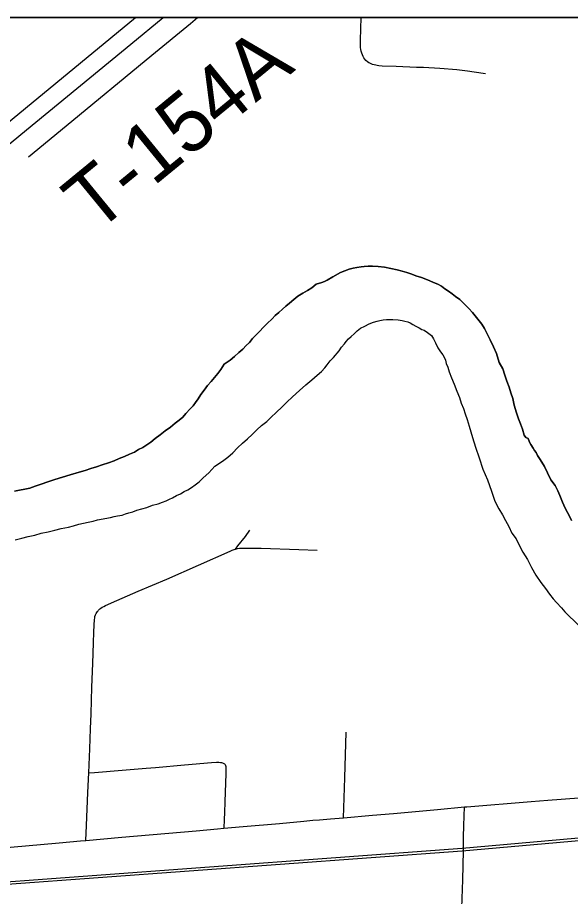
# Model space of a CAD drawing. Extents: x -483 to 680, y 0 to 440.
# Drawn here: x 226.42 to 252.91, y 353.88 to 395.95 of the extents above; entities that cross this region are included whole.
import ezdxf

# ---------------------------------------------------------------- set-up
doc = ezdxf.new("R2010")
doc.units = 0
for name, color, linetype in [('GM_X_City_Street', 7, 'Continuous'), ('GM_X_County_Road', 7, 'Continuous'), ('GM_X_Major_River', 7, 'Continuous'), ('GM_X_Rail_Line', 7, 'Continuous'), ('GM_X_Township_Road', 7, 'Continuous'), ('GM_X_Township_Road_Text', 7, 'Continuous'), ('GM_X_US_Route', 7, 'Continuous'), ('SH_Cut_Line', 7, 'Continuous'), ('SH_Text', 7, 'Continuous')]:
    doc.layers.add(name, color=color, linetype=linetype)

msp = doc.modelspace()

# ---------------------------------------------------------------- linework, layer by layer
at = {"layer": 'GM_X_City_Street'}
for points in [[(236.867, 370.51), (236.981, 370.655), (237.338, 371.112), (237.555, 371.41)], [(229.691, 356.565), (229.72, 357.268), (229.787, 358.859), (229.833, 359.797), (229.878, 360.945), (229.919, 361.898), (229.942, 362.622), (229.978, 363.895), (230.023, 365.032), (230.063, 366.023), (230.079, 366.525), (230.095, 366.862), (230.109, 367.137), (230.118, 367.201), (230.129, 367.273), (230.157, 367.359), (230.185, 367.417), (230.214, 367.468), (230.249, 367.518), (230.28, 367.555), (230.3, 367.579), (230.329, 367.608), (230.37, 367.643), (230.417, 367.68), (230.481, 367.722), (230.553, 367.763), (230.639, 367.805), (231.179, 368.042), (232.204, 368.487), (233.575, 369.073), (236.614, 370.415), (236.699, 370.448), (236.792, 370.485), (236.867, 370.51), (236.965, 370.533), (237.058, 370.546), (237.15, 370.55), (237.492, 370.553), (238.086, 370.545), (239.89, 370.494), (240.774, 370.462)], [(242.045, 357.645), (242.102, 359.552), (242.168, 361.741)], [(231.427, 359.917), (232.591, 360.017), (233.032, 360.054), (234.419, 360.182), (235.713, 360.287), (235.948, 360.301), (236.058, 360.304), (236.141, 360.297), (236.2, 360.287), (236.24, 360.275), (236.273, 360.263), (236.305, 360.244), (236.334, 360.223), (236.363, 360.197), (236.39, 360.152), (236.404, 360.094), (236.404, 360.049), (236.404, 359.987), (236.398, 359.771), (236.35, 358.406), (236.33, 357.9), (236.317, 357.558), (236.301, 357.146)], [(229.833, 359.797), (230.111, 359.818), (231.427, 359.917)], [(247.69, 352.678), (247.71, 353.329), (247.75, 354.672), (247.782, 356.062), (247.793, 356.718), (247.802, 357.277), (247.829, 358.163)]]:
    msp.add_lwpolyline(points, dxfattribs=at)
at = {"layer": 'GM_X_County_Road'}
for points in [[(251.82, 358.489), (253.312, 358.607), (254.357, 358.688), (257.026, 358.902)], [(247.829, 358.163), (247.944, 358.173), (251.024, 358.426), (251.82, 358.489)], [(242.045, 357.645), (243.42, 357.768), (244.44, 357.853), (246.548, 358.041), (247.829, 358.163)], [(236.301, 357.146), (237.231, 357.222), (238.964, 357.379), (240.137, 357.477), (240.571, 357.523), (240.886, 357.548), (241.408, 357.589), (242.045, 357.645)], [(229.691, 356.565), (231.412, 356.711), (234.972, 357.023), (235.994, 357.121), (236.301, 357.146)], [(205.564, 353.935), (206.643, 354.063), (208.428, 354.314), (210.423, 354.623), (211.709, 354.85), (212.757, 354.996), (214.54, 355.211), (216.405, 355.37), (218.975, 355.594), (220.273, 355.721), (221.078, 355.802), (222.285, 355.9), (224.792, 356.123), (226.091, 356.246), (228.412, 356.45), (229.432, 356.543), (229.691, 356.565)]]:
    msp.add_lwpolyline(points, dxfattribs=at)
at = {"layer": 'GM_X_Major_River'}
for points in [[(252.966, 371.875), (252.876, 372.049), (252.767, 372.26), (252.658, 372.472), (252.533, 372.76), (252.407, 373.067), (252.299, 373.297), (252.173, 373.548), (251.97, 373.819), (251.808, 374.165), (251.663, 374.453), (251.536, 374.665), (251.426, 374.839), (251.335, 374.993), (251.262, 375.128), (251.189, 375.225), (251.116, 375.341), (251.006, 375.514), (250.952, 375.629), (250.88, 375.802), (250.767, 375.843), (250.694, 375.959), (250.607, 376.246), (250.518, 376.495), (250.429, 376.744), (250.322, 377.032), (250.218, 377.395), (250.15, 377.72), (250.061, 377.988), (249.973, 378.256), (249.866, 378.544), (249.76, 378.831), (249.672, 379.137), (249.49, 379.446), (249.368, 379.867), (249.224, 380.193), (249.061, 380.52), (248.917, 380.809), (248.79, 381.059), (248.662, 381.271), (248.22, 381.833), (248.035, 382.027), (247.85, 382.222), (247.609, 382.456), (247.404, 382.594), (247.236, 382.731), (247.068, 382.85), (246.9, 382.968), (246.732, 383.086), (246.564, 383.185), (246.357, 383.266), (246.169, 383.347), (245.981, 383.428), (245.774, 383.509), (245.51, 383.592), (245.304, 383.673), (245.078, 383.754), (244.851, 383.817), (244.606, 383.88), (244.304, 383.945), (244.002, 384.01), (243.698, 384.036), (243.433, 384.043), (243.224, 384.048), (243.033, 384.034), (242.881, 384.019), (242.671, 383.986), (242.5, 383.953), (242.308, 383.901), (241.887, 383.74), (241.521, 383.541), (241.251, 383.377), (241.135, 383.323), (241.001, 383.269), (240.733, 383.181), (240.52, 383.015), (240.308, 382.888), (240.096, 382.76), (239.845, 382.615)], [(239.845, 382.615), (240.096, 382.76), (240.308, 382.888), (240.52, 383.015), (240.733, 383.181), (241.001, 383.269), (241.135, 383.323), (241.251, 383.377), (241.521, 383.541), (241.887, 383.74), (242.308, 383.901), (242.5, 383.953), (242.671, 383.986), (242.881, 384.019), (243.033, 384.034), (243.224, 384.048), (243.433, 384.043), (243.698, 384.036), (244.002, 384.01), (244.304, 383.945), (244.606, 383.88), (244.851, 383.817), (245.078, 383.754), (245.304, 383.673), (245.51, 383.592), (245.774, 383.509), (245.981, 383.428), (246.169, 383.347), (246.357, 383.266), (246.564, 383.185), (246.732, 383.086), (246.9, 382.968), (247.068, 382.85), (247.236, 382.731), (247.404, 382.594), (247.609, 382.456), (247.85, 382.222), (248.035, 382.027), (248.22, 381.833), (248.662, 381.271), (248.79, 381.059), (248.917, 380.809), (249.061, 380.52), (249.224, 380.193), (249.368, 379.867), (249.49, 379.446), (249.672, 379.137), (249.76, 378.831), (249.866, 378.544), (249.973, 378.256), (250.061, 377.988), (250.15, 377.72), (250.218, 377.395), (250.322, 377.032), (250.429, 376.744), (250.518, 376.495), (250.607, 376.246), (250.694, 375.959), (250.767, 375.843), (250.88, 375.802), (250.952, 375.629), (251.006, 375.514), (251.116, 375.341), (251.189, 375.225), (251.262, 375.128), (251.335, 374.993), (251.426, 374.839), (251.536, 374.665), (251.663, 374.453), (251.808, 374.165), (251.97, 373.819), (252.173, 373.548), (252.299, 373.297), (252.407, 373.067), (252.533, 372.76), (252.658, 372.472), (252.767, 372.26), (252.876, 372.049), (252.966, 371.875)], [(239.845, 382.615), (239.651, 382.449), (239.457, 382.283), (239.282, 382.135), (239.108, 381.988), (238.933, 381.84), (238.758, 381.693), (238.621, 381.525), (238.388, 381.303), (237.842, 380.747), (237.686, 380.58), (237.529, 380.394), (237.374, 380.246), (237.217, 380.079), (237.024, 379.913), (236.81, 379.729), (236.615, 379.544), (236.326, 379.361), (236.167, 379.099), (236.011, 378.913), (235.854, 378.728), (235.697, 378.523), (235.522, 378.337), (235.364, 378.113), (235.207, 377.908), (235.069, 377.703), (234.95, 377.516), (234.833, 377.367), (234.696, 377.219), (234.481, 376.996), (234.344, 376.829), (234.17, 376.681), (233.976, 376.534), (233.743, 376.35), (233.492, 376.167), (233.259, 375.983), (233.008, 375.799), (232.814, 375.633), (232.621, 375.505), (232.428, 375.377), (232.216, 375.268), (232.023, 375.14), (231.793, 375.051), (231.543, 374.944), (231.293, 374.836), (231.044, 374.728), (230.776, 374.64), (230.469, 374.534), (230.201, 374.446), (229.933, 374.358), (229.665, 374.269), (229.378, 374.182), (228.938, 374.06), (228.574, 373.955), (228.21, 373.832), (227.866, 373.726), (227.559, 373.62), (227.272, 373.513), (227.004, 373.425), (226.278, 373.273)], [(226.278, 373.273), (227.004, 373.425), (227.272, 373.513), (227.559, 373.62), (227.866, 373.726), (228.21, 373.832), (228.574, 373.955), (228.938, 374.06), (229.378, 374.182), (229.665, 374.269), (229.933, 374.358), (230.201, 374.446), (230.469, 374.534), (230.776, 374.64), (231.044, 374.728), (231.293, 374.836), (231.543, 374.944), (231.793, 375.051), (232.023, 375.14), (232.216, 375.268), (232.428, 375.377), (232.621, 375.505), (232.814, 375.633), (233.008, 375.799), (233.259, 375.983), (233.492, 376.167), (233.743, 376.35), (233.976, 376.534), (234.17, 376.681), (234.344, 376.829), (234.481, 376.996), (234.696, 377.219), (234.833, 377.367), (234.95, 377.516), (235.069, 377.703), (235.207, 377.908), (235.364, 378.113), (235.522, 378.337), (235.697, 378.523), (235.854, 378.728), (236.011, 378.913), (236.167, 379.099), (236.326, 379.361), (236.615, 379.544), (236.81, 379.729), (237.024, 379.913), (237.217, 380.079), (237.374, 380.246), (237.529, 380.394), (237.686, 380.58), (237.842, 380.747), (238.388, 381.303), (238.621, 381.525), (238.758, 381.693), (238.933, 381.84), (239.108, 381.988), (239.282, 382.135), (239.457, 382.283), (239.651, 382.449), (239.845, 382.615)], [(226.315, 370.955), (226.621, 371.023), (226.927, 371.11), (227.251, 371.178), (227.557, 371.265), (227.882, 371.333), (228.207, 371.42), (228.513, 371.488), (228.856, 371.555), (229.105, 371.625), (229.353, 371.695), (229.583, 371.746), (229.812, 371.797), (230.041, 371.848), (230.251, 371.9), (230.881, 372.017), (231.053, 372.069), (231.206, 372.103), (231.435, 372.136), (231.588, 372.189), (231.76, 372.241), (231.951, 372.294), (232.143, 372.365), (232.373, 372.435), (232.622, 372.504), (232.89, 372.611), (233.158, 372.681), (233.368, 372.751), (233.541, 372.823), (233.695, 372.895), (233.849, 372.967), (234.041, 373.076), (234.233, 373.147), (234.407, 373.257), (234.58, 373.347), (234.754, 373.457), (234.928, 373.585), (235.121, 373.733), (235.316, 373.917), (235.588, 374.158), (235.881, 374.473), (236.247, 374.711), (236.499, 374.913), (236.732, 375.116), (236.966, 375.357), (237.2, 375.579), (237.433, 375.782), (237.666, 375.985), (237.88, 376.208), (238.114, 376.429), (238.365, 376.613), (238.56, 376.798), (238.832, 377.057), (239.085, 377.297), (239.319, 377.538), (239.592, 377.797), (239.922, 378.093), (240.233, 378.37), (240.524, 378.609), (240.776, 378.831), (240.99, 379.015), (241.146, 379.182), (241.263, 379.331), (241.401, 379.518), (241.557, 379.685), (241.831, 380.001), (241.949, 380.169), (242.086, 380.336), (242.165, 380.448), (242.282, 380.578), (242.399, 380.689), (242.554, 380.818), (242.69, 380.947), (242.845, 381.076), (243.057, 381.185), (243.269, 381.294), (243.479, 381.364), (243.652, 381.417), (243.785, 381.451), (243.938, 381.485), (244.091, 381.501), (244.242, 381.497), (244.394, 381.493), (244.66, 381.486), (244.849, 381.443), (244.981, 381.421), (245.113, 381.38), (245.226, 381.339), (245.357, 381.26), (245.507, 381.18)], [(226.315, 370.955), (226.621, 371.023), (226.927, 371.11), (227.251, 371.178), (227.557, 371.265), (227.882, 371.333), (228.207, 371.42), (228.513, 371.488), (228.856, 371.555), (229.105, 371.625), (229.353, 371.695), (229.583, 371.746), (229.812, 371.797), (230.041, 371.848), (230.251, 371.9), (230.881, 372.017), (231.053, 372.069), (231.206, 372.103), (231.435, 372.136), (231.588, 372.189), (231.76, 372.241), (231.951, 372.294), (232.143, 372.365), (232.373, 372.435), (232.622, 372.504), (232.89, 372.611), (233.158, 372.681), (233.368, 372.751), (233.541, 372.823), (233.695, 372.895), (233.849, 372.967), (234.041, 373.076), (234.233, 373.147), (234.407, 373.257), (234.58, 373.347), (234.754, 373.457), (234.928, 373.585), (235.121, 373.733), (235.316, 373.917), (235.588, 374.158), (235.881, 374.473), (236.247, 374.711), (236.499, 374.913), (236.732, 375.116), (236.966, 375.357), (237.2, 375.579), (237.433, 375.782), (237.666, 375.985), (237.88, 376.208), (238.114, 376.429), (238.365, 376.613), (238.56, 376.798), (238.832, 377.057), (239.085, 377.297), (239.319, 377.538), (239.592, 377.797), (239.922, 378.093), (240.233, 378.37), (240.524, 378.609), (240.776, 378.831), (240.99, 379.015), (241.146, 379.182), (241.263, 379.331), (241.401, 379.518), (241.557, 379.685), (241.831, 380.001), (241.949, 380.169), (242.086, 380.336), (242.165, 380.448), (242.282, 380.578), (242.399, 380.689), (242.554, 380.818), (242.69, 380.947), (242.845, 381.076), (243.057, 381.185), (243.269, 381.294), (243.479, 381.364), (243.652, 381.417), (243.785, 381.451), (243.938, 381.485), (244.091, 381.501), (244.242, 381.497), (244.394, 381.493), (244.66, 381.486), (244.849, 381.443), (244.981, 381.421), (245.113, 381.38), (245.226, 381.339), (245.357, 381.26), (245.507, 381.18)], [(245.507, 381.18), (245.657, 381.1), (245.788, 381.021), (245.901, 380.98), (246.069, 380.881), (246.255, 380.724), (246.347, 380.57), (246.437, 380.378), (246.564, 380.147), (246.692, 379.953), (246.802, 379.799), (246.875, 379.664), (246.929, 379.549), (246.963, 379.396), (247.034, 379.223), (247.105, 378.993), (247.211, 378.706), (247.337, 378.399), (247.462, 378.073), (247.587, 377.766), (247.675, 377.498), (247.782, 377.229), (247.871, 376.98), (247.959, 376.712), (248.065, 376.386), (248.223, 375.851), (248.363, 375.391), (248.54, 374.874), (248.717, 374.338), (248.932, 373.82), (249.127, 373.283), (249.286, 372.804), (249.486, 372.438), (249.649, 372.149), (249.795, 371.88), (249.958, 371.591), (250.102, 371.264), (250.304, 370.993), (250.467, 370.666), (250.63, 370.358), (250.849, 370.011), (251.049, 369.626), (251.249, 369.26), (251.487, 368.912), (251.707, 368.622), (251.909, 368.351), (252.075, 368.119), (252.241, 367.944), (252.482, 367.69), (252.648, 367.496), (253.316, 366.853)], [(245.507, 381.18), (245.657, 381.1), (245.788, 381.021), (245.901, 380.98), (246.069, 380.881), (246.255, 380.724), (246.347, 380.57), (246.437, 380.378), (246.564, 380.147), (246.692, 379.953), (246.802, 379.799), (246.875, 379.664), (246.929, 379.549), (246.963, 379.396), (247.034, 379.223), (247.105, 378.993), (247.211, 378.706), (247.337, 378.399), (247.462, 378.073), (247.587, 377.766), (247.675, 377.498), (247.782, 377.229), (247.871, 376.98), (247.959, 376.712), (248.065, 376.386), (248.223, 375.851), (248.363, 375.391), (248.54, 374.874), (248.717, 374.338), (248.932, 373.82), (249.127, 373.283), (249.286, 372.804), (249.486, 372.438), (249.649, 372.149), (249.795, 371.88), (249.958, 371.591), (250.102, 371.264), (250.304, 370.993), (250.467, 370.666), (250.63, 370.358), (250.849, 370.011), (251.049, 369.626), (251.249, 369.26), (251.487, 368.912), (251.707, 368.622), (251.909, 368.351), (252.075, 368.119), (252.241, 367.944), (252.482, 367.69), (252.648, 367.496), (253.316, 366.853)]]:
    msp.add_lwpolyline(points, dxfattribs=at)
at = {"layer": 'GM_X_Rail_Line'}
for points in [[(192.002, 351.898), (217.44, 353.96), (247.719, 356.19), (265.52, 357.763), (271.346, 358.204), (275.686, 358.582), (279.482, 359.105), (282.993, 359.77), (284.746, 360.25), (290.709, 361.561), (295.027, 362.596), (299.03, 363.462), (304.742, 364.758), (307.834, 365.462), (310.741, 366.066), (314.003, 366.596), (317.177, 366.86), (319.571, 366.986), (330.057, 366.697), (343.63, 366.245), (363.661, 365.604), (385.277, 364.912), (385.608, 364.901)], [(192.012, 351.774), (217.193, 353.826), (247.729, 356.066), (265.613, 357.65), (271.48, 358.071), (275.702, 358.458), (279.502, 358.983), (283.021, 359.649), (284.775, 360.129), (290.737, 361.44), (295.055, 362.475), (299.057, 363.34), (304.769, 364.637), (307.861, 365.341), (310.764, 365.944), (314.018, 366.472), (317.185, 366.736), (319.573, 366.862), (330.054, 366.573), (343.626, 366.12), (363.658, 365.479), (385.273, 364.788), (385.608, 364.776)]]:
    msp.add_lwpolyline(points, dxfattribs=at)
at = {"layer": 'GM_X_Township_Road'}
for points in [[(226.948, 389.291), (228.745, 390.774), (232.848, 394.152), (234.701, 395.667), (235.044, 395.95)], [(245.877, 393.553), (245.528, 393.566), (244.568, 393.605), (243.886, 393.629), (243.733, 393.641), (243.656, 393.649), (243.579, 393.664), (243.5, 393.683), (243.431, 393.703), (243.36, 393.729), (243.292, 393.761), (243.247, 393.788), (243.182, 393.839), (243.108, 393.902), (243.057, 393.959), (243.012, 394.024), (242.972, 394.092), (242.94, 394.162), (242.911, 394.241), (242.885, 394.34), (242.869, 394.428), (242.859, 394.525), (242.853, 394.867), (242.891, 395.95)], [(248.844, 393.259), (248.721, 393.275), (247.983, 393.386), (247.46, 393.453), (246.654, 393.509), (245.877, 393.553)]]:
    msp.add_lwpolyline(points, dxfattribs=at)
at = {"layer": 'GM_X_US_Route'}
for points in [[(206.38, 374.838), (215.072, 381.962), (232.066, 395.95)], [(207.104, 374.34), (210.386, 377.035), (213.272, 379.399), (215.577, 381.295), (226.858, 390.579), (231.856, 394.683), (233.393, 395.95)]]:
    msp.add_lwpolyline(points, dxfattribs=at)
at = {"layer": 'SH_Cut_Line'}
msp.add_lwpolyline([(385.608, 55.95), (385.608, 395.95), (45.608, 395.95), (45.608, 281.486), (47.873, 281.454), (57.759, 281.293), (64.783, 281.226), (67.114, 281.188), (73.333, 281.086), (75.975, 281.043), (77.151, 281.034), (77.105, 279.466), (77.065, 275.738), (77.043, 273.874), (76.996, 269.37), (76.941, 265.642), (76.868, 261.138), (76.791, 256.013), (76.689, 249.801), (76.636, 246.539)], dxfattribs=at)
at = {"layer": 'SH_Text'}
msp.add_lwpolyline([(45.608, 395.95), (385.608, 395.95), (385.608, 55.95), (45.608, 55.95)], close=True, dxfattribs=at)

# ---------------------------------------------------------------- texts
at = {"layer": 'GM_X_Township_Road_Text'}
msp.add_text('T-154A', height=2.8409, rotation=39.335, dxfattribs=at).set_placement((230.148, 385.565))

doc.saveas('drawing.dxf')
